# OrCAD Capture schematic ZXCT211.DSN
size Custom; title: ZXCT211, 26V, ZERO-DRIFT, HIGH PRECISION CURRENT MONITOR; rev: 1.0; note: DS45449 Rev. 2 - 2
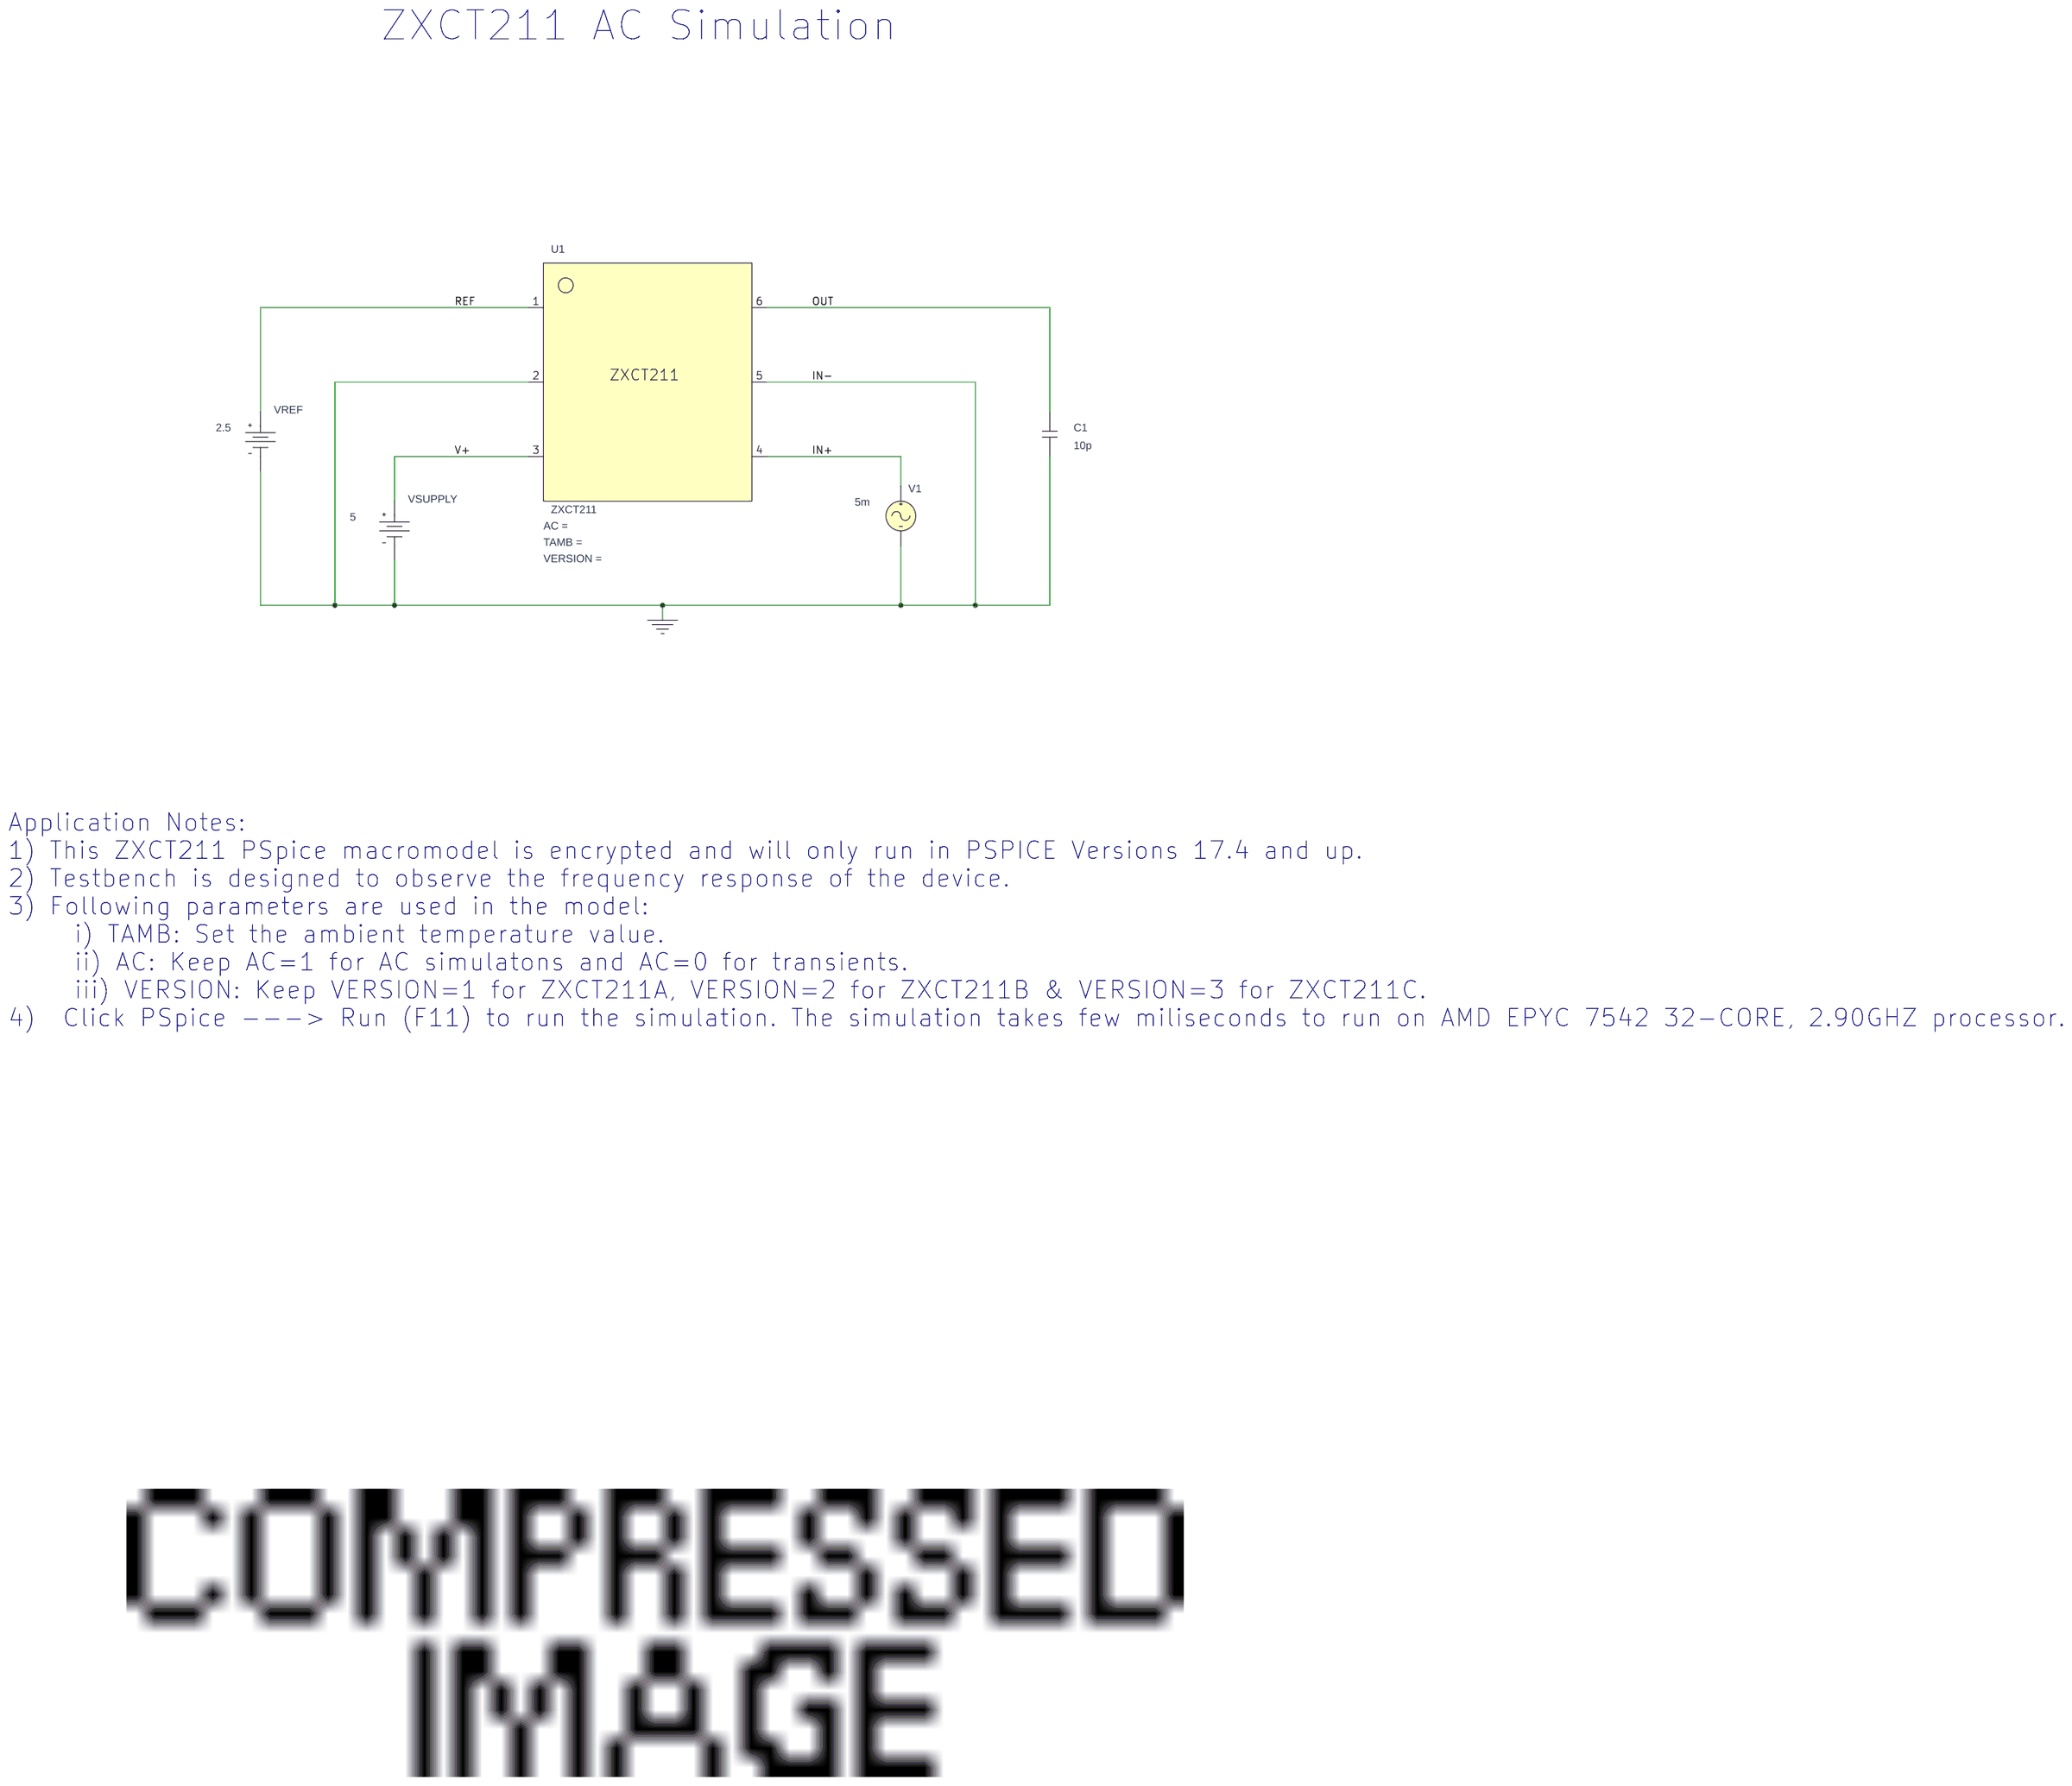
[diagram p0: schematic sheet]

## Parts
C1  10p  [RAD/CK05]
U1  ZXCT211
V1  VAC
VREF  VDC
VSUPPLY  VDC

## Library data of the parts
C1 = C
U1 = ZXCT211
V1 = VAC: ACMAG: 5m
VREF = VDC: DC: 2.5
VSUPPLY = VDC: DC: 5

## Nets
0: C1.2 U1.2(GND) U1.5(IN-) V1.2(-) VREF.1(-) VSUPPLY.1(-)
IN+: U1.4(IN+) V1.1(+)
OUT: C1.1 U1.6(OUT)
REF: U1.1(REF) VREF.0(+)
V+: U1.3(V+) VSUPPLY.0(+)

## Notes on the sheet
- ZXCT211 AC Simulation
- Application Notes:
  1) This ZXCT211 PSpice macromodel is encrypted and will only run in PSPICE Versions 17.4 and up.
  2) Testbench is designed to observe the frequency response of the device.
  3) Following parameters are used in the model:
       i) TAMB: Set the ambient temperature value.
       ii) AC: Keep AC=1 for AC simulatons and AC=0 for transients.
       iii) VERSION: Keep VERSION=1 for ZXCT211A, VERSION=2 for ZXCT211B & VERSION=3 for ZXCT211C.
  4)  Click PSpice ---> Run (F11) to run the simulation. The simulation takes few miliseconds to run on AMD EPYC 7542 32-CORE, 2.90GHZ processor.
